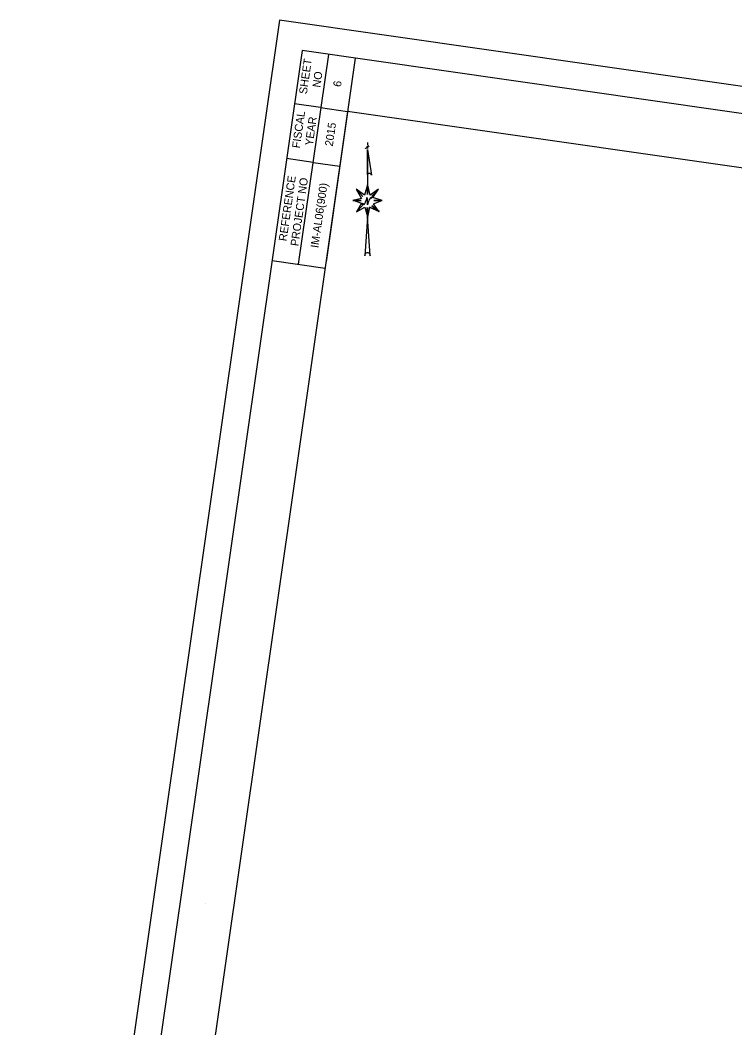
# Model space of a CAD drawing. Extents: x 1797205 to 1798536, y 248101 to 249940.
# Drawn here: x 1797205 to 1797871, y 249003 to 249940 of the extents above; entities that cross this region are included whole.
import ezdxf

# ---------------------------------------------------------------- set-up
doc = ezdxf.new("R2010")
doc.units = 0
for name, color, linetype in [('ANNO-SHT', 7, 'Continuous'), ('DRAINAGE', 7, 'Continuous'), ('Level 1', 7, 'Continuous'), ('Level 57', 7, 'Continuous'), ('Level 6', 7, 'Continuous'), ('Level 62', 7, 'Continuous'), ('SHT-BDR', 7, 'Continuous'), ('SHT-BNDRY', 7, 'Continuous')]:
    doc.layers.add(name, color=color, linetype=linetype)

# ---------------------------------------------------------------- blocks, each defined once
blk = doc.blocks.new('SC47208')
at = {"layer": 'Level 1'}
blk.add_line((0, 0), (0, 0), dxfattribs=at)

msp = doc.modelspace()

# ---------------------------------------------------------------- linework, layer by layer
at = {"layer": 'Level 57'}
msp.add_line((1797528.83, 249826.25), (1797528.71, 249823.79), dxfattribs=at)
for points in [[(1797529.91, 249822.72), (1797529.81, 249822.66), (1797529.88, 249822.52), (1797529.98, 249822.68), (1797529.95, 249822.83), (1797529.72, 249822.82), (1797529.45, 249822.7), (1797529.34, 249822.57), (1797529.12, 249822.23), (1797529.02, 249821.8), (1797528.79, 249821.2), (1797528.73, 249821.06), (1797528.63, 249820.64), (1797528.63, 249821.25), (1797528.55, 249822.19), (1797528.37, 249822.81), (1797528.38, 249822.22), (1797528.61, 249820.67), (1797528.55, 249822.2), (1797528.37, 249822.82), (1797528.24, 249822.24), (1797527.84, 249821.2), (1797527.55, 249820.64), (1797527.33, 249820.59), (1797527.05, 249820.59), (1797526.97, 249820.64), (1797526.97, 249820.88), (1797527.07, 249820.96), (1797527.15, 249820.9), (1797527.1, 249820.78)], [(1797528.71, 249819.73), (1797532.37, 249795.62), (1797532.22, 249796.37), (1797532.02, 249796.67), (1797531.62, 249797), (1797531.11, 249797.26), (1797530.79, 249797.32), (1797530.43, 249797.31), (1797530.03, 249797.35), (1797529.74, 249797.21), (1797529.42, 249797.08), (1797529.06, 249796.81), (1797528.9, 249796.57), (1797528.75, 249796.26), (1797528.72, 249796.13), (1797528.73, 249819.56), (1797528.84, 249786.65)], [(1797528.75, 249786.65), (1797528.64, 249777.75), (1797528.75, 249786.74), (1797526.05, 249777.14), (1797518.18, 249782.69), (1797524.29, 249775.99), (1797518.18, 249782.69), (1797523.11, 249774.14), (1797515.13, 249772.2), (1797522.76, 249772.03), (1797515.25, 249772.38), (1797523, 249769.56), (1797518.42, 249761.72), (1797524.17, 249767.45), (1797518.42, 249761.72), (1797526.29, 249766.04), (1797528.64, 249757.14), (1797528.52, 249765.51), (1797528.64, 249756.96), (1797530.63, 249765.95), (1797539.56, 249761.81), (1797530.51, 249765.95), (1797528.64, 249756.7), (1797526.27, 249720.71), (1797526.45, 249721.88), (1797526.79, 249722.64), (1797527.26, 249723.18), (1797527.88, 249723.61), (1797528.43, 249723.73), (1797529.05, 249723.71), (1797529.57, 249723.53), (1797530.09, 249723.22), (1797530.5, 249722.69), (1797530.87, 249722.05), (1797531, 249721.58), (1797531.15, 249720.67), (1797528.74, 249757.23), (1797530.5, 249766.04), (1797539.42, 249761.81), (1797532.61, 249767.09), (1797539.31, 249761.99), (1797534.14, 249769.03), (1797542.13, 249772.12), (1797534.49, 249772.03), (1797542.36, 249772.12), (1797533.55, 249774.85), (1797539.07, 249782.69), (1797532.61, 249776.34), (1797539.07, 249782.69), (1797531.09, 249777.14), (1797528.85, 249786.56)], [(1797532.63, 249774.66), (1797532.4, 249774.46), (1797532.71, 249774.23), (1797532.85, 249774.56), (1797532.76, 249774.93), (1797532.67, 249775.06), (1797532, 249774.96), (1797531.42, 249774.7), (1797530.4, 249773.46), (1797530.27, 249773.03), (1797529.91, 249771.82), (1797529.46, 249770.56), (1797528.97, 249769.69), (1797528.8, 249768.29), (1797528.8, 249770.06), (1797528.62, 249772.29), (1797528.53, 249773.49), (1797528.04, 249774.93), (1797528, 249773.23), (1797528.26, 249770.96), (1797528.49, 249769.52), (1797528.8, 249768.35), (1797528.75, 249770.39), (1797528.57, 249773.53), (1797528, 249774.96), (1797527.68, 249773.46), (1797527.06, 249771.86), (1797526.75, 249771.22), (1797526.53, 249770.36), (1797526.13, 249769.62), (1797525.81, 249769.09), (1797525.55, 249768.52), (1797524.75, 249768.15), (1797524.12, 249768.29), (1797523.85, 249768.55), (1797523.81, 249769.25), (1797524.21, 249769.55), (1797524.52, 249769.19), (1797524.26, 249768.95)]]:
    msp.add_lwpolyline(points, dxfattribs=at)
at = {"layer": 'Level 6'}
for p, q in [((1797492.31, 249908.11), (1797464.32, 249712.83)), ((1797517.31, 249904.53), (1797490.18, 249715.23)), ((1797484.86, 249858.65), (1797460.76, 249862.11)), ((1797484.86, 249858.65), (1797510.21, 249855.02)), ((1797478.21, 249807.63), (1797453.46, 249811.18)), ((1797478.21, 249807.63), (1797502.91, 249804.09)), ((1797439.87, 249716.33), (1797489.32, 249709.24))]:
    msp.add_line(p, q, dxfattribs=at)
at = {"layer": 'Level 62'}
msp.add_lwpolyline([(1798294.36, 248101.04), (1798535.54, 249783.85), (1797446.66, 249939.91), (1797205.48, 248257.1)], close=True, dxfattribs=at)
at = {"layer": 'SHT-BDR'}
msp.add_lwpolyline([(1798237.8, 248235.41), (1798450.6, 249720.24), (1797510.21, 249855.02), (1797297.4, 248370.19)], close=True, dxfattribs=at)
at = {"layer": 'SHT-BNDRY'}
msp.add_lwpolyline([(1798278.47, 248166.46), (1798507.24, 249762.65), (1797467.86, 249911.62), (1797239.09, 248315.42)], close=True, dxfattribs=at)

# ---------------------------------------------------------------- block references
at = {"layer": 'DRAINAGE', "xscale": 1.0000020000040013, "yscale": 1.0000020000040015, "rotation": -34.57277348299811}
msp.add_blockref('SC47208', (1797378.36, 249117.87), dxfattribs=at)
msp.add_blockref('SC47208', (1797378.36, 249117.87), dxfattribs=at)

# ---------------------------------------------------------------- texts
at = {"layer": 'ANNO-SHT'}
for s, height, p in [('6', 7.45, (1797503.98, 249877.48)), ('2015', 7.449, (1797496.36, 249822.2)), ('IM-AL06(900)', 7.4493, (1797482.97, 249727.67))]:
    msp.add_text(s, height=height, rotation=81.84389, dxfattribs=at).set_placement(p)
at = {"layer": 'Level 6'}
for s, p in [('SHEET', (1797472.25, 249870.75)), ('NO', (1797484.75, 249876.89)), ('FISCAL', (1797465.74, 249820.43)), ('YEAR', (1797477.7, 249822.76)), ('REFERENCE', (1797453.35, 249733.96)), ('PROJECT NO', (1797464.31, 249729.36))]:
    msp.add_text(s, height=7.442, rotation=81.84389, dxfattribs=at).set_placement(p)

doc.saveas('drawing.dxf')
